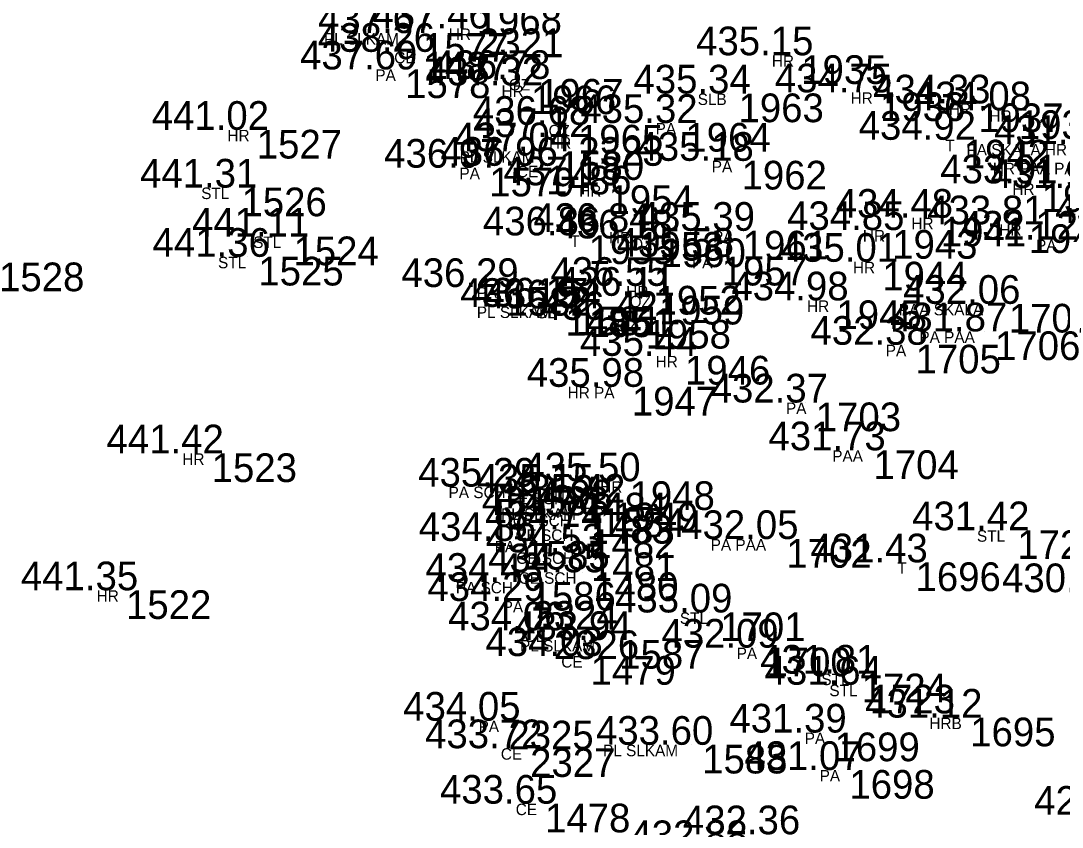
# Model space of a CAD drawing. Extents: x -639390 to -639075, y -1138747 to -1138358.
# Drawn here: x -639290.05 to -639262.82, y -1138562.26 to -1138541.18 of the extents above; entities that cross this region are included whole.
import ezdxf

# ---------------------------------------------------------------- set-up
doc = ezdxf.new("R2010")
doc.units = 0
for name, color, linetype in [('Vrstva 11', 7, 'Continuous'), ('Vrstva 12', 7, 'Continuous'), ('Vrstva 13', 7, 'Continuous'), ('Vrstva 57', 7, 'Continuous')]:
    doc.layers.add(name, color=color, linetype=linetype)

msp = doc.modelspace()

# ---------------------------------------------------------------- linework, layer by layer
at = {"layer": 'Vrstva 11'}
for p, q in [((-639278.37, -1138541.38), (-639278.37, -1138541.38)), ((-639279.81, -1138541.5), (-639279.81, -1138541.5)), ((-639279.8, -1138541.99), (-639279.8, -1138541.99)), ((-639269.92, -1138542.08), (-639269.92, -1138542.08)), ((-639280.28, -1138542.45), (-639280.28, -1138542.45)), ((-639276.8, -1138542.7), (-639276.8, -1138542.7)), ((-639276.99, -1138542.87), (-639276.99, -1138542.87)), ((-639267.86, -1138543.05), (-639267.86, -1138543.05)), ((-639271.56, -1138543.08), (-639271.56, -1138543.08)), ((-639265.29, -1138543.34), (-639265.29, -1138543.34)), ((-639264.23, -1138543.52), (-639264.23, -1138543.52)), ((-639272.95, -1138543.85), (-639272.95, -1138543.85)), ((-639284.16, -1138544.03), (-639284.16, -1138544.03)), ((-639275.76, -1138543.9), (-639275.76, -1138543.9)), ((-639275.75, -1138544.22), (-639275.75, -1138544.22)), ((-639265.67, -1138544.29), (-639265.67, -1138544.29)), ((-639276.26, -1138544.59), (-639276.26, -1138544.59)), ((-639271.48, -1138544.84), (-639271.48, -1138544.84)), ((-639278.08, -1138545.02), (-639278.08, -1138545.02)), ((-639276.59, -1138544.97), (-639276.59, -1138544.97)), ((-639274.96, -1138545.48), (-639274.96, -1138545.48)), ((-639263.63, -1138545.43), (-639263.63, -1138545.43)), ((-639284.56, -1138545.54), (-639284.56, -1138545.54)), ((-639266.27, -1138546.33), (-639266.27, -1138546.33)), ((-639263.97, -1138546.5), (-639263.97, -1138546.5)), ((-639283.2, -1138546.82), (-639283.2, -1138546.82)), ((-639275.48, -1138546.79), (-639275.48, -1138546.79)), ((-639274.18, -1138546.7), (-639274.18, -1138546.7)), ((-639273.6, -1138546.87), (-639273.6, -1138546.87)), ((-639271.45, -1138546.67), (-639271.45, -1138546.67)), ((-639267.54, -1138546.65), (-639267.54, -1138546.65)), ((-639263, -1138546.9), (-639263, -1138546.9)), ((-639284.12, -1138547.35), (-639284.12, -1138547.35)), ((-639272, -1138547.35), (-639272, -1138547.35)), ((-639267.8, -1138547.48), (-639267.8, -1138547.48)), ((-639277.63, -1138548.14), (-639277.63, -1138548.14)), ((-639273.73, -1138548.11), (-639273.73, -1138548.11)), ((-639273.64, -1138548.37), (-639273.64, -1138548.37)), ((-639269, -1138548.49), (-639269, -1138548.49)), ((-639276.09, -1138548.66), (-639276.09, -1138548.66)), ((-639275.81, -1138548.65), (-639275.81, -1138548.65)), ((-639275.48, -1138548.7), (-639275.48, -1138548.7)), ((-639264.49, -1138548.58), (-639264.49, -1138548.58)), ((-639273.99, -1138549), (-639273.99, -1138549)), ((-639264.85, -1138549.3), (-639264.85, -1138549.3)), ((-639266.93, -1138549.65), (-639266.93, -1138549.65)), ((-639272.96, -1138549.94), (-639272.96, -1138549.94)), ((-639274.35, -1138550.75), (-639274.35, -1138550.75)), ((-639269.54, -1138551.16), (-639269.54, -1138551.16)), ((-639285.34, -1138552.49), (-639285.34, -1138552.49)), ((-639268.03, -1138552.41), (-639268.03, -1138552.41)), ((-639277.19, -1138553.36), (-639277.19, -1138553.36)), ((-639274.41, -1138553.22), (-639274.41, -1138553.22)), ((-639275.66, -1138553.52), (-639275.66, -1138553.52)), ((-639275.18, -1138553.93), (-639275.18, -1138553.93)), ((-639274.84, -1138553.78), (-639274.84, -1138553.78)), ((-639275.51, -1138554.1), (-639275.51, -1138554.1)), ((-639275.44, -1138554.48), (-639275.44, -1138554.48)), ((-639264.27, -1138554.5), (-639264.27, -1138554.5)), ((-639270.31, -1138554.73), (-639270.31, -1138554.73)), ((-639277.16, -1138554.78), (-639277.16, -1138554.78)), ((-639275.42, -1138555.08), (-639275.42, -1138555.08)), ((-639266.93, -1138555.34), (-639266.93, -1138555.34)), ((-639277, -1138555.85), (-639277, -1138555.85)), ((-639275.36, -1138555.6), (-639275.36, -1138555.6)), ((-639287.58, -1138556.07), (-639287.58, -1138556.07)), ((-639276.95, -1138556.35), (-639276.95, -1138556.35)), ((-639272.04, -1138556.65), (-639272.04, -1138556.65)), ((-639276.39, -1138557.12), (-639276.39, -1138557.12)), ((-639274.68, -1138557.37), (-639274.68, -1138557.37)), ((-639270.83, -1138557.57), (-639270.83, -1138557.57)), ((-639275.43, -1138557.79), (-639275.43, -1138557.79)), ((-639268.34, -1138558.25), (-639268.34, -1138558.25)), ((-639268.13, -1138558.54), (-639268.13, -1138558.54)), ((-639265.5, -1138559.4), (-639265.5, -1138559.4)), ((-639277.58, -1138559.48), (-639277.58, -1138559.48)), ((-639269.05, -1138559.79), (-639269.05, -1138559.79)), ((-639277.01, -1138560.2), (-639277.01, -1138560.2)), ((-639272.51, -1138560.11), (-639272.51, -1138560.11)), ((-639268.66, -1138560.77), (-639268.66, -1138560.77)), ((-639276.62, -1138561.65), (-639276.62, -1138561.65))]:
    msp.add_line(p, q, dxfattribs=at)

# ---------------------------------------------------------------- texts
at = {"layer": 'Vrstva 12'}
for s, p in [('437.67 ', (-639282.279, -1138541.5)), ('437.46 ', (-639280.856, -1138541.38)), ('438.26 ', (-639282.286, -1138541.99)), ('435.15 ', (-639272.39, -1138542.08)), ('437.69 ', (-639282.749, -1138542.45)), ('436.78 ', (-639279.269, -1138542.7)), ('437.32 ', (-639279.459, -1138542.87)), ('435.34 ', (-639274.029, -1138543.08)), ('434.75 ', (-639270.33, -1138543.05)), ('434.33 ', (-639267.759, -1138543.34)), ('434.08 ', (-639266.699, -1138543.52)), ('441.02 ', (-639286.629, -1138544.03)), ('436.68 ', (-639278.229, -1138543.9)), ('435.32 ', (-639275.419, -1138543.85)), ('437.12 ', (-639278.219, -1138544.22)), ('434.92 ', (-639268.139, -1138544.29)), ('437.04 ', (-639278.729, -1138544.59)), ('431.69 ', (-639264.599, -1138544.4)), ('435.18 ', (-639273.949, -1138544.84)), ('436.97 ', (-639280.549, -1138545.02)), ('436.96 ', (-639279.076, -1138544.97)), ('433.91 ', (-639266.005, -1138545.43)), ('441.31 ', (-639286.935, -1138545.54)), ('437.13 ', (-639277.429, -1138545.48)), ('431.92 ', (-639264.689, -1138545.55)), ('434.48 ', (-639268.739, -1138546.33)), ('433.81 ', (-639266.345, -1138546.5)), ('432.98 ', (-639262.999, -1138546.47)), ('436.86 ', (-639277.966, -1138546.79)), ('436.84 ', (-639276.649, -1138546.7)), ('435.39 ', (-639273.919, -1138546.67)), ('434.85 ', (-639270.01, -1138546.65)), ('441.11 ', (-639285.575, -1138546.82)), ('436.18 ', (-639276.069, -1138546.87)), ('432.12 ', (-639265.469, -1138546.9)), ('441.36 ', (-639286.606, -1138547.35)), ('435.58 ', (-639274.469, -1138547.35)), ('435.01 ', (-639270.175, -1138547.48)), ('436.29 ', (-639280.099, -1138548.14)), ('436.55 ', (-639276.2, -1138548.11)), ('436.11 ', (-639276.015, -1138548.37)), ('436.19 ', (-639278.559, -1138548.66)), ('436.17 ', (-639278.279, -1138548.65)), ('436.54 ', (-639277.949, -1138548.7)), ('434.98 ', (-639271.469, -1138548.49)), ('432.06 ', (-639266.976, -1138548.58)), ('436.42 ', (-639276.459, -1138549)), ('431.87 ', (-639267.319, -1138549.3)), ('432.38 ', (-639269.399, -1138549.65)), ('435.44 ', (-639275.429, -1138549.94)), ('435.98 ', (-639276.819, -1138550.75)), ('432.37 ', (-639272.009, -1138551.16)), ('441.42 ', (-639287.809, -1138552.49)), ('431.73 ', (-639270.499, -1138552.41)), ('435.50 ', (-639276.909, -1138553.22)), ('435.29 ', (-639279.659, -1138553.36)), ('435.15 ', (-639278.13, -1138553.52)), ('435.42 ', (-639277.309, -1138553.78)), ('434.96 ', (-639277.996, -1138554.1)), ('434.98 ', (-639277.649, -1138553.93)), ('434.74 ', (-639277.909, -1138554.48)), ('431.42 ', (-639266.739, -1138554.5)), ('434.86 ', (-639279.646, -1138554.78)), ('432.05 ', (-639272.78, -1138554.73)), ('434.53 ', (-639277.889, -1138555.08)), ('431.43 ', (-639269.399, -1138555.34)), ('434.35 ', (-639277.83, -1138555.6)), ('441.35 ', (-639290.05, -1138556.07)), ('434.43 ', (-639279.469, -1138555.85)), ('434.29 ', (-639279.419, -1138556.35)), ('430.87 ', (-639264.389, -1138556.12)), ('433.09 ', (-639274.509, -1138556.65)), ('434.06 ', (-639278.876, -1138557.12)), ('433.94 ', (-639277.149, -1138557.37)), ('432.09 ', (-639273.299, -1138557.57)), ('434.03 ', (-639277.899, -1138557.79)), ('431.81 ', (-639270.715, -1138558.25)), ('431.64 ', (-639270.599, -1138558.54)), ('434.05 ', (-639280.05, -1138559.48)), ('431.12 ', (-639267.969, -1138559.4)), ('431.39 ', (-639271.519, -1138559.79)), ('433.60 ', (-639275.009, -1138560.11)), ('433.72 ', (-639279.479, -1138560.2)), ('431.07 ', (-639271.129, -1138560.77)), ('433.65 ', (-639279.09, -1138561.65)), ('429.16 ', (-639263.546, -1138561.94)), ('432.36 ', (-639272.736, -1138562.45)), ('432.88 ', (-639274.109, -1138562.84))]:
    msp.add_text(s, height=0.75, dxfattribs=at).set_placement(p)
at = {"layer": 'Vrstva 13'}
for s, p in [(' 1968', (-639278.41, -1138541.53)), (' 2321', (-639278.37, -1138542.13)), (' 1577', (-639279.81, -1138542.25)), (' 1487', (-639279.8, -1138542.74)), (' 1935', (-639269.92, -1138542.83)), (' 1578', (-639280.28, -1138543.2)), (' 1967', (-639276.8, -1138543.45)), (' 1966', (-639276.99, -1138543.62)), (' 1936', (-639267.86, -1138543.8)), (' 1963', (-639271.56, -1138543.83)), (' 1937', (-639265.29, -1138544.09)), (' 1938', (-639264.23, -1138544.27)), (' 1964', (-639272.95, -1138544.6)), (' 1527', (-639284.16, -1138544.78)), (' 1965', (-639275.76, -1138544.65)), (' 2323', (-639275.75, -1138544.97)), (' 1942', (-639265.67, -1138545.04)), (' 1580', (-639276.26, -1138545.34)), (' 1486', (-639276.59, -1138545.72)), (' 1962', (-639271.48, -1138545.59)), (' 1579', (-639278.08, -1138545.77)), (' 1954', (-639274.96, -1138546.23)), (' 1939', (-639263.63, -1138546.18)), (' 1526', (-639284.56, -1138546.29)), (' 1941', (-639266.27, -1138547.08)), (' 1940', (-639263.97, -1138547.25)), (' 1524', (-639283.2, -1138547.57)), (' 1955', (-639275.48, -1138547.54)), (' 1953', (-639274.18, -1138547.45)), (' 1960', (-639273.6, -1138547.62)), (' 1961', (-639271.45, -1138547.42)), (' 1943', (-639267.54, -1138547.4)), (' 1525', (-639284.12, -1138548.1)), (' 1957', (-639272, -1138548.1)), (' 1528', (-639290.9, -1138548.25)), (' 1944', (-639267.8, -1138548.23)), (' 1582', (-639277.63, -1138548.89)), (' 1952', (-639273.73, -1138548.86)), (' 1959', (-639273.64, -1138549.12)), (' 1945', (-639269, -1138549.24)), (' 1485', (-639276.09, -1138549.41)), (' 1581', (-639275.81, -1138549.4)), (' 1951', (-639275.48, -1138549.45)), (' 1707', (-639264.49, -1138549.33)), (' 1958', (-639273.99, -1138549.75)), (' 1706', (-639264.85, -1138550.05)), (' 1705', (-639266.93, -1138550.4)), (' 1946', (-639272.96, -1138550.69)), (' 1947', (-639274.35, -1138551.5)), (' 1703', (-639269.54, -1138551.91)), (' 1523', (-639285.34, -1138553.24)), (' 1704', (-639268.03, -1138553.16)), (' 1583', (-639277.19, -1138554.11)), (' 1948', (-639274.41, -1138553.97)), (' 1484', (-639275.66, -1138554.27)), (' 1584', (-639275.18, -1138554.68)), (' 1949', (-639274.84, -1138554.53)), (' 1483', (-639275.51, -1138554.85)), (' 1482', (-639275.44, -1138555.23)), (' 1722', (-639264.27, -1138555.25)), (' 1585', (-639277.16, -1138555.53)), (' 1702', (-639270.31, -1138555.48)), (' 1481', (-639275.42, -1138555.83)), (' 1480', (-639275.36, -1138556.35)), (' 1696', (-639266.93, -1138556.09)), (' 1586', (-639277, -1138556.6)), (' 1522', (-639287.58, -1138556.82)), (' 2324', (-639276.95, -1138557.1)), (' 1701', (-639272.04, -1138557.4)), (' 2326', (-639276.39, -1138557.87)), (' 1587', (-639274.68, -1138558.12)), (' 1700', (-639270.83, -1138558.32)), (' 1479', (-639275.43, -1138558.54)), (' 1724', (-639268.34, -1138559)), (' 1723', (-639268.13, -1138559.29)), (' 1695', (-639265.5, -1138560.15)), (' 2325', (-639277.58, -1138560.23)), (' 1699', (-639269.05, -1138560.54)), (' 2327', (-639277.01, -1138560.95)), (' 1588', (-639272.51, -1138560.86)), (' 1698', (-639268.66, -1138561.52)), (' 1478', (-639276.62, -1138562.4))]:
    msp.add_text(s, height=0.75, dxfattribs=at).set_placement(p)
at = {"layer": 'Vrstva 57'}
for s, p in [('HR', (-639278.859, -1138541.68)), ('PL SLKAM', (-639282.125, -1138541.8)), ('CE', (-639280.287, -1138542.29)), ('HR', (-639270.409, -1138542.38)), ('PA', (-639280.78, -1138542.75)), ('OZ', (-639277.289, -1138543)), ('HR', (-639277.479, -1138543.17)), ('HR', (-639268.349, -1138543.35)), ('SLB', (-639272.349, -1138543.38)), ('HR', (-639265.779, -1138543.64)), ('HR', (-639264.719, -1138543.82)), ('PA', (-639273.45, -1138544.15)), ('HR', (-639284.649, -1138544.33)), ('OZ', (-639276.249, -1138544.2)), ('HR', (-639276.239, -1138544.52)), ('T', (-639265.87, -1138544.59)), ('PA SKALA HR', (-639265.319, -1138544.7)), ('PL SLKAM', (-639278.575, -1138544.89)), ('CE', (-639277.078, -1138545.27)), ('PA', (-639271.98, -1138545.14)), ('HR PAA PA SKALA', (-639264.63, -1138545.19)), ('PA', (-639278.58, -1138545.32)), ('HR', (-639275.449, -1138545.78)), ('HR', (-639264.119, -1138545.73)), ('STL', (-639285.335, -1138545.84)), ('HR', (-639266.759, -1138546.63)), ('HR', (-639264.459, -1138546.8)), ('STL', (-639283.975, -1138547.12)), ('T', (-639275.68, -1138547.09)), ('HR', (-639274.669, -1138547)), ('OZ', (-639274.089, -1138547.17)), ('PA', (-639271.95, -1138546.97)), ('HR', (-639268.029, -1138546.95)), ('PA', (-639263.5, -1138547.2)), ('STL', (-639284.895, -1138547.65)), ('PA', (-639272.5, -1138547.65)), ('HR', (-639268.289, -1138547.78)), ('PA', (-639278.13, -1138548.44)), ('HR', (-639274.219, -1138548.41)), ('OZ', (-639274.129, -1138548.67)), ('HR', (-639269.489, -1138548.79)), ('PL SLKAM', (-639278.125, -1138548.95)), ('CE', (-639276.578, -1138548.96)), ('T', (-639275.68, -1138549)), ('PAA SKALA', (-639267.09, -1138548.88)), ('OZ', (-639274.479, -1138549.3)), ('PA PAA', (-639266.55, -1138549.6)), ('PA', (-639267.43, -1138549.95)), ('HR', (-639273.449, -1138550.24)), ('HR PA', (-639275.75, -1138551.05)), ('PA', (-639270.04, -1138551.46)), ('HR', (-639285.829, -1138552.79)), ('PAA', (-639268.83, -1138552.71)), ('PA SCH', (-639278.865, -1138553.66)), ('HR', (-639274.899, -1138553.52)), ('CE SCH', (-639277.335, -1138553.82)), ('PL SLKAM', (-639277.495, -1138554.23)), ('HR', (-639275.329, -1138554.08)), ('CE SCH', (-639277.185, -1138554.4)), ('CE SCH', (-639277.115, -1138554.78)), ('STL', (-639265.045, -1138554.8)), ('PA PAA', (-639272.01, -1138555.03)), ('PA', (-639277.66, -1138555.08)), ('CE SCH', (-639277.095, -1138555.38)), ('T', (-639267.13, -1138555.64)), ('PA SCH', (-639278.675, -1138556.15)), ('CE SCH', (-639277.035, -1138555.9)), ('HR', (-639288.069, -1138556.37)), ('PA', (-639277.45, -1138556.65)), ('STL', (-639272.815, -1138556.95)), ('CE', (-639276.878, -1138557.42)), ('PL SLKAM', (-639276.995, -1138557.67)), ('PA', (-639271.33, -1138557.87)), ('CE', (-639275.917, -1138558.09)), ('STL', (-639269.115, -1138558.55)), ('STL', (-639268.905, -1138558.84)), ('HRB', (-639266.289, -1138559.7)), ('PA', (-639278.08, -1138559.78)), ('PA', (-639269.55, -1138560.09)), ('CE', (-639277.498, -1138560.5)), ('PL SLKAM', (-639274.825, -1138560.41)), ('PA', (-639269.16, -1138561.07)), ('CE', (-639277.108, -1138561.95))]:
    msp.add_text(s, height=0.3, dxfattribs=at).set_placement(p)

doc.saveas('drawing.dxf')
